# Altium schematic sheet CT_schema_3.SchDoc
size 184 x 159 mm
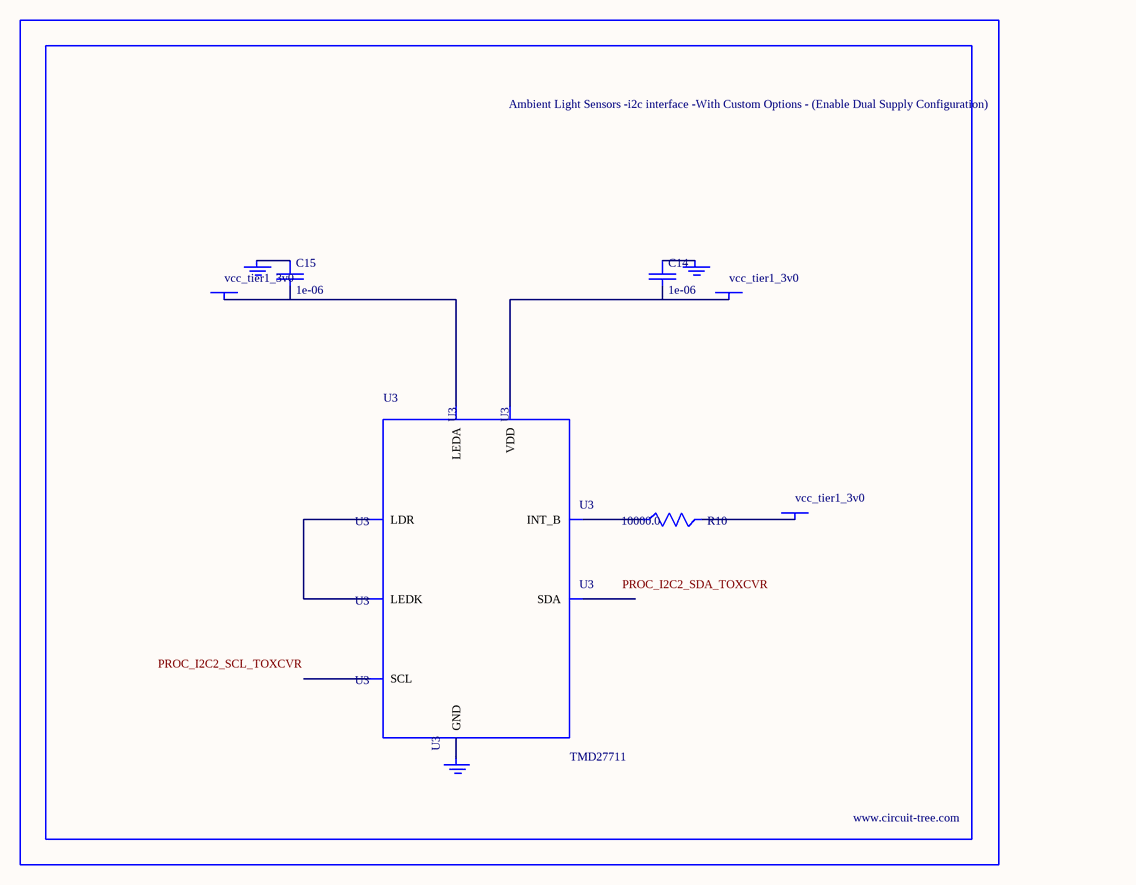
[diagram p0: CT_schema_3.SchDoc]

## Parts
BORDER2  (no value)
C14  1e-06  [C0603]
C15  1e-06  [C0603]
GND_INSTANCE_2_0  (no value)
GND_INSTANCE_2_1  (no value)
GND_INSTANCE_2_2  (no value)
POWER_INSTANCE_2_0  vcc_tier1_3v0
POWER_INSTANCE_2_1  vcc_tier1_3v0
POWER_INSTANCE_2_2  vcc_tier1_3v0
R10  10000.0  [R0603]
U3  TMD27711  [SMD-8]

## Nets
NetC14_1: C14.1 GND_INSTANCE_2_0.0(GND)
NetC14_2: C14.2 POWER_INSTANCE_2_0.0(PWR) U3.1(VDD)
NetC15_1: C15.1 GND_INSTANCE_2_1.0(GND)
NetC15_2: C15.2 POWER_INSTANCE_2_1.0(PWR) U3.4(LEDA)
NetGND_INSTANCE_2_2_0: GND_INSTANCE_2_2.0(GND) U3.3(GND)
NetPOWER_INSTANCE_2_2_0: POWER_INSTANCE_2_2.0(PWR) R10.2
NetR10_1: R10.1 U3.7(INT_B)
NetU3_5: U3.5(LEDK) U3.6(LDR)

Not connected (* = marked no-connect by the designer): U3 2(SCL) 8(SDA)

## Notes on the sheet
- Labels drawn without touching a wire or pin: PROC_I2C2_SCL_TOXCVR, PROC_I2C2_SDA_TOXCVR

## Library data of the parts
BORDER2 = BORDER_PAGE2
C14 C15 = C0603C105K3RACTU
GND_INSTANCE_2_0-GND_INSTANCE_2_2 = GND
POWER_INSTANCE_2_0-POWER_INSTANCE_2_2 = PWR
R10 = RC0603JR-0710KL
